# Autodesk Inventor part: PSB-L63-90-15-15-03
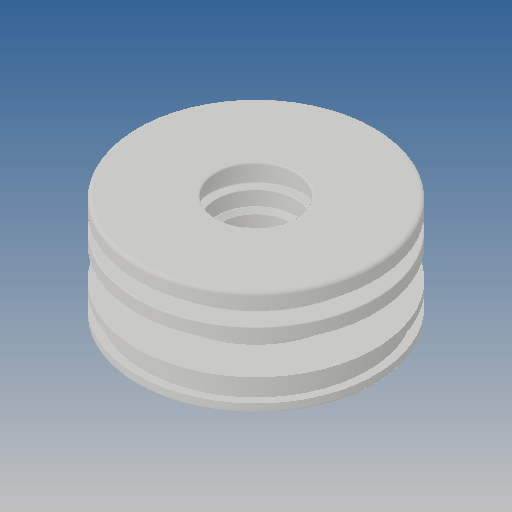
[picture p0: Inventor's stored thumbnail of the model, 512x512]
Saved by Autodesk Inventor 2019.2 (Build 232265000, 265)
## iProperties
Created: 2013-04
Part Number: PSB-L63-90-15-15-03
Material: Ogólny
Document SubType Name: Modeling
Designer: CADENGINEERING4
Density: 1 g/cm^3
Appearance: Domyślna
Author: CADENGINEERING4
Revision Number: ÈÎºÎ
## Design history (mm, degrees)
feature "µ¹½Ç1"
node "Bryła1"
